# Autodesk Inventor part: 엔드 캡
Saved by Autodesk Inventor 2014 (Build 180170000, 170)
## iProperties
Created: 2025-12
Part Number: 엔드 캡
Material: 일반
Document SubType Name: Modeling
Designer: dg
Density: 1 g/cm^3
Appearance: 기본값
Author: dg
Author: jhkim
Creation Date: 2025-11-19
Sending System: Autodesk Inventor 2026
Preprocessor: ST-DEVELOPER v20.1
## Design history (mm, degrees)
node "엔드 캡1"
node "솔리드1"
node "기준1"
